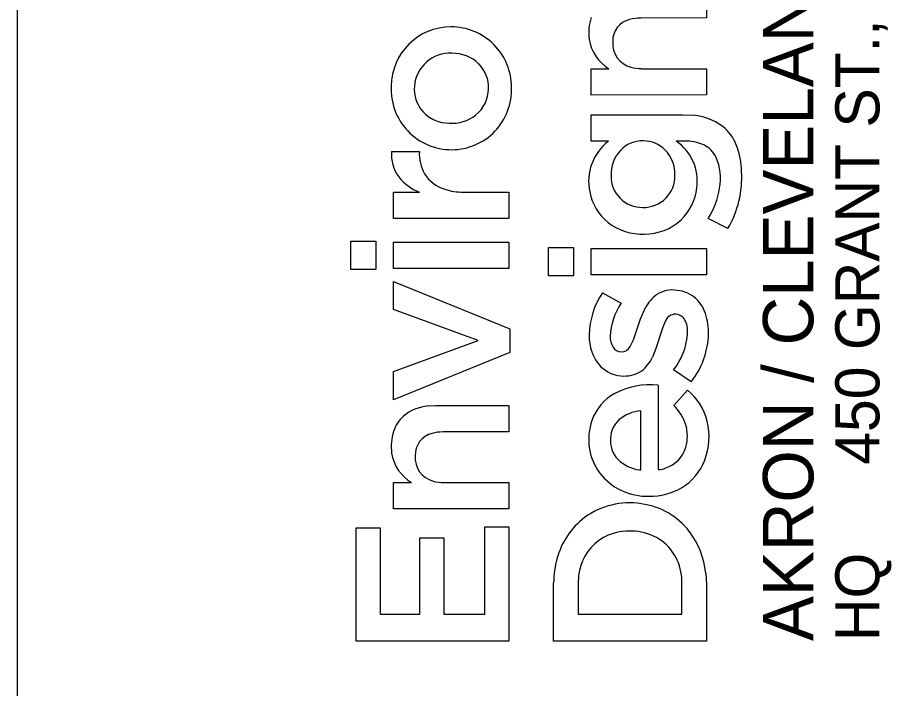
# Model space of a CAD drawing. Extents: x 0 to 1700, y 0 to 1100.
# Drawn here: x 1600 to 1649.43, y 129.22 to 167.17 of the extents above; entities that cross this region are included whole.
import ezdxf

# ---------------------------------------------------------------- set-up
doc = ezdxf.new("R2010")
doc.units = 0
doc.layers.add('SH_Border', color=7, linetype='Continuous')
doc.layers.add('SH_Data', color=7, linetype='Continuous')

msp = doc.modelspace()

# ---------------------------------------------------------------- linework, layer by layer
at = {"layer": 'SH_Border'}
msp.add_line((1600, 25), (1600, 1075), dxfattribs=at)
at = {"layer": 'SH_Data'}
for p, q in [((1638.958, 168.633), (1638.958, 167.144)), ((1638.958, 167.144), (1635.242, 167.14)), ((1632.444, 164.275), (1633.449, 164.277)), ((1632.444, 162.785), (1632.444, 164.275)), ((1635.284, 164.277), (1638.957, 164.277)), ((1638.957, 164.277), (1638.958, 162.789)), ((1638.958, 162.789), (1632.444, 162.785)), ((1632.445, 160.168), (1632.445, 161.661)), ((1632.445, 161.661), (1637.618, 161.661)), ((1637.618, 161.661), (1638.096, 161.643)), ((1633.418, 160.168), (1632.445, 160.168)), ((1637.881, 160.178), (1637.243, 160.181)), ((1621.149, 159.597), (1622.727, 159.597)), ((1621.271, 155.797), (1621.271, 157.289)), ((1621.271, 157.289), (1622.736, 157.289)), ((1625.206, 157.29), (1627.786, 157.287)), ((1627.786, 157.287), (1627.782, 155.797)), ((1627.782, 155.797), (1621.271, 155.797)), ((1640.18, 155.245), (1639.06, 155.799)), ((1618.853, 152.909), (1618.853, 154.513)), ((1618.853, 154.513), (1620.272, 154.513)), ((1620.272, 154.513), (1620.272, 152.909)), ((1621.271, 152.971), (1621.271, 154.464)), ((1621.271, 154.464), (1627.786, 154.464)), ((1627.786, 154.464), (1627.786, 152.971)), ((1630.025, 152.555), (1630.025, 154.159)), ((1630.025, 154.159), (1631.444, 154.159)), ((1631.444, 154.159), (1631.444, 152.555)), ((1632.444, 152.617), (1632.444, 154.11)), ((1632.444, 154.11), (1638.958, 154.11)), ((1638.958, 154.11), (1638.958, 152.617)), ((1620.272, 152.909), (1618.853, 152.909)), ((1627.786, 152.971), (1621.271, 152.971)), ((1631.444, 152.555), (1630.025, 152.555)), ((1638.958, 152.617), (1632.444, 152.617)), ((1621.271, 150.663), (1621.271, 152.23)), ((1621.271, 152.23), (1627.835, 149.565)), ((1633.076, 151.603), (1634.134, 151.013)), ((1635.242, 150.129), (1635.518, 150.763)), ((1626.058, 148.899), (1621.271, 150.663)), ((1634.837, 148.934), (1635.242, 150.129)), ((1636.671, 150.05), (1636.492, 149.665)), ((1627.835, 149.565), (1627.835, 148.22)), ((1636.492, 149.665), (1636.106, 148.441)), ((1621.271, 147.147), (1626.058, 148.899)), ((1634.649, 148.558), (1634.837, 148.934)), ((1636.106, 148.441), (1635.911, 147.96)), ((1627.835, 148.22), (1621.271, 145.543)), ((1621.271, 145.543), (1621.271, 147.147)), ((1638.107, 146.571), (1637.099, 147.235)), ((1636.226, 146.373), (1636.232, 141.597)), ((1637.114, 145.232), (1637.884, 146.1)), ((1623.219, 145.199), (1623.645, 145.222)), ((1623.645, 145.222), (1627.785, 145.222)), ((1627.785, 145.222), (1627.786, 143.732)), ((1635.245, 141.591), (1635.245, 144.917)), ((1627.786, 143.732), (1624.07, 143.729)), ((1635.18, 141.583), (1635.245, 141.591)), ((1621.271, 140.864), (1622.276, 140.866)), ((1621.271, 139.373), (1621.271, 140.864)), ((1624.111, 140.866), (1627.785, 140.866)), ((1627.785, 140.866), (1627.786, 139.378)), ((1627.786, 139.378), (1621.271, 139.373)), ((1619.149, 131.896), (1619.149, 138.299)), ((1619.149, 138.299), (1620.506, 138.299)), ((1620.506, 138.299), (1620.506, 133.413)), ((1626.428, 133.413), (1626.428, 138.361)), ((1626.428, 138.361), (1627.786, 138.361)), ((1627.786, 138.361), (1627.786, 131.896)), ((1622.752, 133.413), (1622.752, 137.744)), ((1622.752, 137.744), (1624.109, 137.744)), ((1624.109, 137.744), (1624.109, 133.413)), ((1631.733, 135.589), (1631.703, 135.115)), ((1638.924, 135.748), (1638.958, 135.105)), ((1630.322, 131.899), (1630.322, 135.2)), ((1631.703, 135.115), (1631.703, 133.419)), ((1637.575, 133.417), (1637.576, 135.12)), ((1638.958, 135.105), (1638.958, 131.9)), ((1620.506, 133.413), (1622.752, 133.413)), ((1624.109, 133.413), (1626.428, 133.413)), ((1631.703, 133.419), (1637.575, 133.417)), ((1627.786, 131.896), (1619.149, 131.896)), ((1638.958, 131.9), (1630.322, 131.899))]:
    msp.add_line(p, q, dxfattribs=at)
for points in [[(1634.392, 168.61), (1634.817, 168.633), (1638.958, 168.633), (1638.958, 167.144), (1635.242, 167.14)], [(1632.444, 162.785), (1632.444, 164.275), (1633.449, 164.277)], [(1635.284, 164.277), (1638.957, 164.277), (1638.958, 162.789), (1632.444, 162.785)], [(1633.418, 160.168), (1632.445, 160.168), (1632.445, 161.661), (1637.618, 161.661), (1638.096, 161.643)], [(1637.881, 160.178), (1637.243, 160.181)], [(1621.149, 159.597), (1622.727, 159.597)], [(1625.206, 157.29), (1627.786, 157.287), (1627.782, 155.797), (1621.271, 155.797)], [(1621.271, 155.797), (1621.271, 157.289), (1622.736, 157.289)], [(1640.18, 155.245), (1639.06, 155.799)], [(1633.076, 151.603), (1634.134, 151.013)], [(1634.649, 148.558), (1634.837, 148.934), (1635.242, 150.129), (1635.518, 150.763)], [(1636.671, 150.05), (1636.492, 149.665), (1636.106, 148.441), (1635.911, 147.96)], [(1638.107, 146.571), (1637.099, 147.235)], [(1636.226, 146.373), (1636.232, 141.597)], [(1637.114, 145.232), (1637.884, 146.1)], [(1623.219, 145.199), (1623.645, 145.222), (1627.785, 145.222), (1627.786, 143.732), (1624.07, 143.729)], [(1635.18, 141.583), (1635.245, 141.591), (1635.245, 144.917)], [(1621.271, 139.373), (1621.271, 140.864), (1622.276, 140.866)], [(1624.111, 140.866), (1627.785, 140.866), (1627.786, 139.378), (1621.271, 139.373)], [(1638.924, 135.748), (1638.958, 135.105), (1638.958, 131.9), (1630.322, 131.899)], [(1631.733, 135.589), (1631.703, 135.115), (1631.703, 133.419), (1637.575, 133.417), (1637.576, 135.12)], [(1630.322, 131.899), (1630.322, 135.2)]]:
    msp.add_lwpolyline(points, dxfattribs=at)
for points in [[(1618.853, 152.909), (1618.853, 154.513), (1620.272, 154.513), (1620.272, 152.909)], [(1621.271, 152.971), (1621.271, 154.464), (1627.786, 154.464), (1627.786, 152.971)], [(1630.025, 152.555), (1630.025, 154.159), (1631.444, 154.159), (1631.444, 152.555)], [(1632.444, 152.617), (1632.444, 154.11), (1638.958, 154.11), (1638.958, 152.617)], [(1621.271, 145.543), (1621.271, 147.147), (1626.058, 148.899), (1621.271, 150.663), (1621.271, 152.23), (1627.835, 149.565), (1627.835, 148.22)], [(1619.149, 131.896), (1619.149, 138.299), (1620.506, 138.299), (1620.506, 133.413), (1622.752, 133.413), (1622.752, 137.744), (1624.109, 137.744), (1624.109, 133.413), (1626.428, 133.413), (1626.428, 138.361), (1627.786, 138.361), (1627.786, 131.896)]]:
    msp.add_lwpolyline(points, close=True, dxfattribs=at)
for centre, radius, start, end in [((1635.109, 166.321), 2.801, 162.274, 187.7917), ((1635.109, 166.321), 2.801, 162.274, 187.7917), ((1635.227, 164.84), 2.3, 89.6051, 105.3303), ((1635.227, 164.84), 2.3, 89.6051, 105.3303), ((1624.507, 163.271), 3.37, 89.8476, 179.6405), ((1624.507, 163.271), 3.37, 89.8476, 179.6405), ((1624.529, 163.237), 3.405, 359.5401, 90.2114), ((1624.529, 163.237), 3.405, 359.5401, 90.2114), ((1634.914, 165.845), 1.249, 103.6868, 182.214), ((1634.914, 165.845), 1.249, 103.6868, 182.214), ((1634.686, 166.312), 2.381, 188.9646, 238.6987), ((1634.686, 166.312), 2.381, 188.9646, 238.6987), ((1635.04, 165.69), 1.378, 175.5844, 255.1382), ((1635.04, 165.69), 1.378, 175.5844, 255.1382), ((1624.461, 163.132), 2.02, 87.0481, 175.5726), ((1624.461, 163.132), 2.02, 87.0481, 175.5726), ((1624.602, 163), 2.149, 45.8426, 90.9801), ((1624.602, 163), 2.149, 45.8426, 90.9801), ((1624.729, 163.211), 1.911, 357.8857, 44.159), ((1624.729, 163.211), 1.911, 357.8857, 44.159), ((1635.264, 166.385), 2.107, 254.0891, 270.5284), ((1635.264, 166.385), 2.107, 254.0891, 270.5284), ((1624.541, 163.104), 3.409, 176.8344, 270.4038), ((1624.541, 163.104), 3.409, 176.8344, 270.4038), ((1624.365, 163.125), 1.924, 175.1538, 221.1471), ((1624.365, 163.125), 1.924, 175.1538, 221.1471), ((1624.562, 163.069), 3.374, 270.0624, 2.3776), ((1624.562, 163.069), 3.374, 270.0624, 2.3776), ((1624.723, 163.159), 1.915, 308.2894, 359.4347), ((1624.723, 163.159), 1.915, 308.2894, 359.4347), ((1624.459, 163.303), 2.114, 223.0999, 268.8089), ((1624.459, 163.303), 2.114, 223.0999, 268.8089), ((1624.548, 163.395), 2.209, 266.5651, 308.0608), ((1624.548, 163.395), 2.209, 266.5651, 308.0608), ((1637.953, 158.394), 3.251, 53.4034, 87.4906), ((1637.953, 158.394), 3.251, 53.4034, 87.4906), ((1638.259, 159.02), 2.571, 21.6075, 50.5577), ((1638.259, 159.02), 2.571, 21.6075, 50.5577), ((1635.146, 157.906), 2.846, 127.3748, 192.2247), ((1635.146, 157.906), 2.846, 127.3748, 192.2247), ((1635.347, 158.464), 1.73, 88.473, 136.4256), ((1635.347, 158.464), 1.73, 88.473, 136.4256), ((1635.407, 158.481), 1.712, 44.2719, 90.4762), ((1635.407, 158.481), 1.712, 44.2719, 90.4762), ((1635.71, 157.914), 2.736, 352.1125, 55.923), ((1635.71, 157.914), 2.736, 352.1125, 55.923), ((1637.833, 157.862), 2.316, 65.0169, 88.8011), ((1637.833, 157.862), 2.316, 65.0169, 88.8011), ((1635.571, 158.301), 2.005, 137.4674, 182.3324), ((1635.571, 158.301), 2.005, 137.4674, 182.3324), ((1635.184, 158.3), 1.998, 358.5714, 43.5376), ((1635.184, 158.3), 1.998, 358.5714, 43.5376), ((1638.13, 158.578), 1.543, 26.2681, 63.803), ((1638.13, 158.578), 1.543, 26.2681, 63.803), ((1636.535, 158.357), 4.418, 1.1514, 21.3627), ((1636.535, 158.357), 4.418, 1.1514, 21.3627), ((1623.308, 159.441), 2.164, 175.8731, 216.3475), ((1623.308, 159.441), 2.164, 175.8731, 216.3475), ((1625.043, 159.474), 2.32, 176.9688, 209.6064), ((1625.043, 159.474), 2.32, 176.9688, 209.6064), ((1636.783, 158.077), 2.976, 349.3073, 23.4307), ((1636.783, 158.077), 2.976, 349.3073, 23.4307), ((1624.757, 159.407), 2.039, 211.9447, 253.2028), ((1624.757, 159.407), 2.039, 211.9447, 253.2028), ((1635.323, 158.185), 1.755, 178.8821, 271.0837), ((1635.323, 158.185), 1.755, 178.8821, 271.0837), ((1635.409, 158.202), 1.773, 268.2788, 1.5502), ((1635.409, 158.202), 1.773, 268.2788, 1.5502), ((1635.269, 158.122), 5.692, 329.6388, 3.26), ((1635.269, 158.122), 5.692, 329.6388, 3.26), ((1623.733, 159.858), 2.755, 218.0981, 248.7907), ((1623.733, 159.858), 2.755, 218.0981, 248.7907), ((1625.233, 160.825), 3.535, 252.4655, 269.573), ((1625.233, 160.825), 3.535, 252.4655, 269.573), ((1635.232, 157.848), 2.919, 190.7518, 231.2892), ((1635.232, 157.848), 2.919, 190.7518, 231.2892), ((1635.494, 157.854), 2.944, 313.742, 353.8554), ((1635.494, 157.854), 2.944, 313.742, 353.8554), ((1635.369, 158.167), 4.385, 327.3149, 351.5748), ((1635.369, 158.167), 4.385, 327.3149, 351.5748), ((1635.477, 157.951), 3.026, 269.6361, 312.7088), ((1635.477, 157.951), 3.026, 269.6361, 312.7088), ((1635.316, 158.056), 3.134, 232.4606, 272.5902), ((1635.316, 158.056), 3.134, 232.4606, 272.5902), ((1637.03, 150.13), 1.632, 80.1719, 122.5197), ((1637.03, 150.13), 1.632, 80.1719, 122.5197), ((1636.818, 149.129), 4.486, 146.531, 178.7571), ((1636.818, 149.129), 4.486, 146.531, 178.7571), ((1637.33, 149.856), 2.026, 125.5118, 153.4159), ((1637.33, 149.856), 2.026, 125.5118, 153.4159), ((1637.139, 149.912), 1.834, 47.7934, 84.6892), ((1637.139, 149.912), 1.834, 47.7934, 84.6892), ((1636.894, 149.73), 2.134, 14.9966, 46.2063), ((1636.894, 149.73), 2.134, 14.9966, 46.2063), ((1637.259, 148.945), 3.747, 146.5112, 176.9101), ((1637.259, 148.945), 3.747, 146.5112, 176.9101), ((1637.192, 149.815), 0.571, 76.6609, 155.7053), ((1637.192, 149.815), 0.571, 76.6609, 155.7053), ((1637.199, 149.756), 0.628, 21.5098, 78.5262), ((1637.199, 149.756), 0.628, 21.5098, 78.5262), ((1635.522, 149.337), 3.561, 355.8306, 15.3914), ((1635.522, 149.337), 3.561, 355.8306, 15.3914), ((1636.296, 149.383), 1.605, 354.5726, 22.068), ((1636.296, 149.383), 1.605, 354.5726, 22.068), ((1634.833, 149.119), 2.503, 177.5366, 222.7932), ((1634.833, 149.119), 2.503, 177.5366, 222.7932), ((1634.655, 149.117), 1.138, 178.4747, 211.0868), ((1634.655, 149.117), 1.138, 178.4747, 211.0868), ((1634.124, 149.575), 3.785, 321.811, 354.7969), ((1634.124, 149.575), 3.785, 321.811, 354.7969), ((1634.476, 149.41), 4.609, 321.9777, 355.8738), ((1634.476, 149.41), 4.609, 321.9777, 355.8738), ((1634.166, 148.835), 0.574, 212.2368, 268.3777), ((1634.166, 148.835), 0.574, 212.2368, 268.3777), ((1634.171, 148.795), 0.534, 267.716, 333.7337), ((1634.171, 148.795), 0.534, 267.716, 333.7337), ((1634.049, 148.79), 2.039, 308.0877, 335.9874), ((1634.049, 148.79), 2.039, 308.0877, 335.9874), ((1634.3, 148.767), 1.875, 225.9854, 302.4797), ((1634.3, 148.767), 1.875, 225.9854, 302.4797), ((1635.76, 142.207), 4.192, 83.615, 118.2876), ((1635.76, 142.207), 4.192, 83.615, 118.2876), ((1635.12, 143.453), 2.792, 118.8308, 160.6244), ((1635.12, 143.453), 2.792, 118.8308, 160.6244), ((1635.872, 143.584), 3.222, 13.5336, 51.3615), ((1635.872, 143.584), 3.222, 13.5336, 51.3615), ((1623.435, 142.714), 2.494, 94.9696, 130.2225), ((1623.435, 142.714), 2.494, 94.9696, 130.2225), ((1635.393, 142.805), 2.118, 94.008, 130.8817), ((1635.393, 142.805), 2.118, 94.008, 130.8817), ((1635.189, 143.278), 2.743, 19.0357, 45.4406), ((1635.189, 143.278), 2.743, 19.0357, 45.4406), ((1623.174, 143.131), 2.008, 132.2219, 161.6818), ((1623.174, 143.131), 2.008, 132.2219, 161.6818), ((1635.521, 143.306), 3.219, 160.5201, 215.7831), ((1635.521, 143.306), 3.219, 160.5201, 215.7831), ((1635.024, 143.314), 1.492, 132.9851, 177.179), ((1635.024, 143.314), 1.492, 132.9851, 177.179), ((1635.318, 143.461), 3.79, 339.3542, 13.3785), ((1635.318, 143.461), 3.79, 339.3542, 13.3785), ((1635.535, 143.485), 2.35, 344.6059, 17.007), ((1635.535, 143.485), 2.35, 344.6059, 17.007), ((1623.936, 142.91), 2.801, 162.2736, 187.7919), ((1623.936, 142.91), 2.801, 162.2736, 187.7919), ((1623.741, 142.433), 1.249, 103.6865, 182.2187), ((1623.741, 142.433), 1.249, 103.6865, 182.2187), ((1624.054, 141.428), 2.301, 89.6049, 105.3284), ((1624.054, 141.428), 2.301, 89.6049, 105.3284), ((1635.085, 143.252), 1.557, 175.0013, 223.283), ((1635.085, 143.252), 1.557, 175.0013, 223.283), ((1636.12, 143.357), 1.752, 288.0077, 343.5508), ((1636.12, 143.357), 1.752, 288.0077, 343.5508), ((1623.513, 142.901), 2.381, 188.962, 238.7037), ((1623.513, 142.901), 2.381, 188.962, 238.7037), ((1623.867, 142.279), 1.378, 175.5854, 255.1439), ((1623.867, 142.279), 1.378, 175.5854, 255.1439), ((1635.446, 143.682), 2.116, 225.0619, 262.7974), ((1635.446, 143.682), 2.116, 225.0619, 262.7974), ((1635.947, 143.26), 3.13, 300.9427, 338.7323), ((1635.947, 143.26), 3.13, 300.9427, 338.7323), ((1635.626, 143.527), 3.436, 217.7452, 271.6543), ((1635.626, 143.527), 3.436, 217.7452, 271.6543), ((1636.237, 142.608), 1.01, 269.7003, 294.8711), ((1636.237, 142.608), 1.01, 269.7003, 294.8711), ((1624.092, 142.974), 2.108, 254.0916, 270.5284), ((1624.092, 142.974), 2.108, 254.0916, 270.5284), ((1635.775, 143.62), 3.528, 269.2048, 300.3341), ((1635.775, 143.62), 3.528, 269.2048, 300.3341), ((1634.614, 135.396), 4.321, 81.194, 125.9984), ((1634.614, 135.396), 4.321, 81.194, 125.9984), ((1634.729, 135.566), 4.136, 37.8521, 82.402), ((1634.729, 135.566), 4.136, 37.8521, 82.402), ((1634.693, 135.446), 4.327, 127.2362, 165.148), ((1634.693, 135.446), 4.327, 127.2362, 165.148), ((1634.447, 135.391), 2.699, 106.1881, 157.3861), ((1634.447, 135.391), 2.699, 106.1881, 157.3861), ((1634.639, 134.931), 3.195, 55.6727, 107.2093), ((1634.639, 134.931), 3.195, 55.6727, 107.2093), ((1634.293, 135.283), 4.654, 5.7333, 37.304), ((1634.293, 135.283), 4.654, 5.7333, 37.304), ((1634.646, 135.249), 2.934, 357.4662, 52.2665), ((1634.646, 135.249), 2.934, 357.4662, 52.2665), ((1635.713, 135.141), 5.391, 164.7861, 179.3704), ((1635.713, 135.141), 5.391, 164.7861, 179.3704), ((1634.914, 135.194), 3.206, 157.3571, 172.9275), ((1634.914, 135.194), 3.206, 157.3571, 172.9275)]:
    msp.add_arc(centre, radius, start, end, dxfattribs=at)

# ---------------------------------------------------------------- texts
for s, height, p in [('450 GRANT ST., AKRON, OH  44311', 2.49231, (1648.744, 141.869)), ('AKRON / CLEVELAND / COLUMBUS', 2.84845, (1645.006, 131.9)), ('HQ ', 2.4923, (1648.744, 131.9))]:
    msp.add_text(s, height=height, rotation=90, dxfattribs=at).set_placement(p)

doc.saveas('drawing.dxf')
